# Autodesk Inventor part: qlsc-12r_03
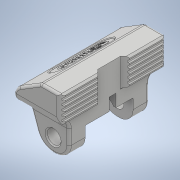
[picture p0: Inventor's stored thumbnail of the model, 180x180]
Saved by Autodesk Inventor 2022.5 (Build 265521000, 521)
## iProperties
Part Number: qlsc-12r_03
Material: 一般
Document SubType Name: Modeling
Designer: ImaoCorp
Density: 1 g/cm^3
Appearance: 既定
Author: ImaoCorp
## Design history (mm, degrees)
feature "qlsc-12r_03"
node "ソリッド1"
